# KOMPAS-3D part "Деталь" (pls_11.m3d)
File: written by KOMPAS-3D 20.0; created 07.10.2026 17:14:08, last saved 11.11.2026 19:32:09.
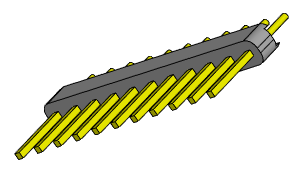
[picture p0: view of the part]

Document properties: Полное имя файла: D:\myProjects\Progect_esp32\box_compas\разъемы\pls_11.m3d

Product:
- Part/product: Деталь
    Масса: 0.00141779

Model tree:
1. Эскиз:1
2. Элемент выдавливания:1
     Расстояние 1 = 2.5
3. Эскиз:2  (with: Элемент выдавливания:1)
4. Элемент выдавливания:2
     Расстояние 1 = 6
5. Массив по сетке:1  (with: Элемент выдавливания:2, Эскиз:2)  (11 pattern instances)
     Шаг 1 = 2.54; Угол раствора = 90
6. Эскиз:3  (with: Элемент выдавливания:1)
7. Элемент выдавливания:3
     Расстояние 1 = 3
8. Массив по сетке:2  (with: Элемент выдавливания:3, Эскиз:3)  (11 pattern instances)
     Шаг 1 = 2.54; Угол раствора = 90; Геометрический массив = 128
9. Эскиз:4  (with: Элемент выдавливания:1)
10. Элемент выдавливания:4
     Расстояние 2 = 27.94
11. Скругление:1  (with: Элемент выдавливания:1)
     Радиус = 1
